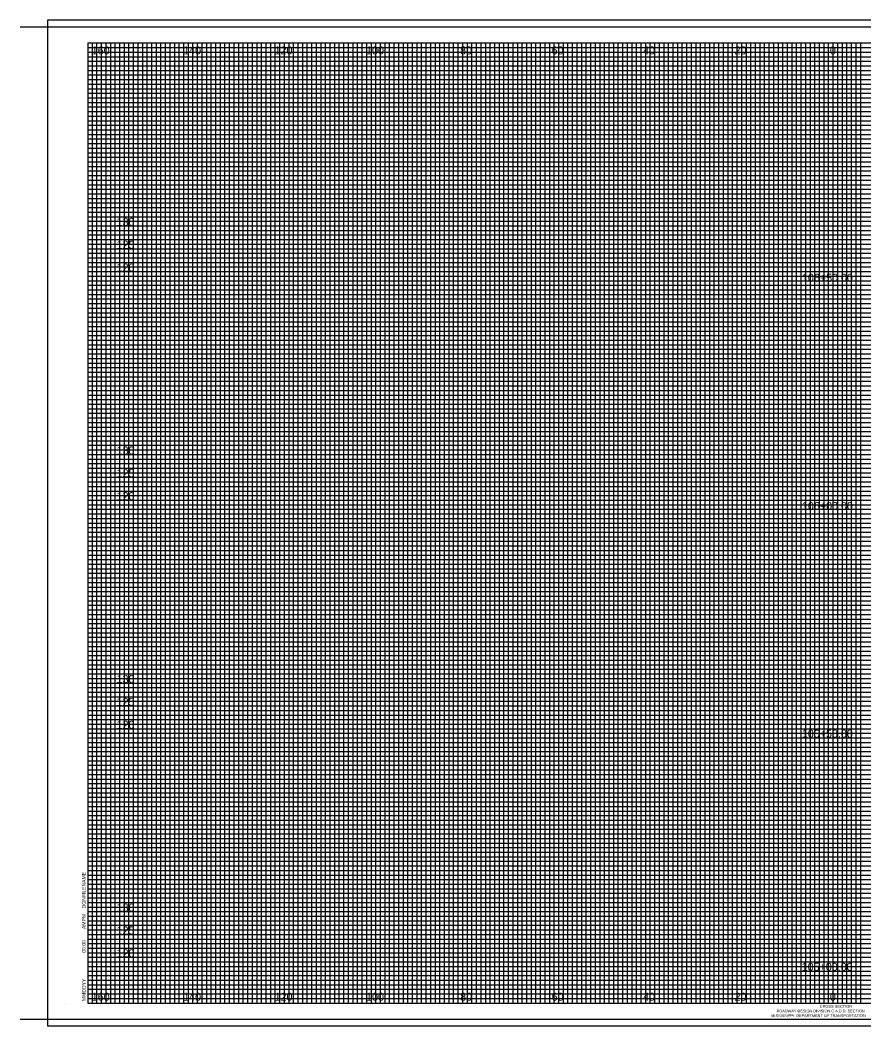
# Model space of a CAD drawing. Extents: x -3604 to 2303, y -13 to 9543.
# Drawn here: x -3604.5 to -3420, y 7144.1 to 7364.1 of the extents above; entities that cross this region are included whole.
import ezdxf

# ---------------------------------------------------------------- set-up
doc = ezdxf.new("R2010")
doc.units = 0
for name, color, linetype in [('SHEET_BORDER', 7, 'Continuous'), ('SHEET_BORDER_TX', 7, 'Continuous'), ('SHEET_DATE_DGN_TX', 7, 'Continuous'), ('SHEET_PLOTTING_SHAPE', 7, 'Continuous'), ('XS_SHEET_LABELS_ELEVATION', 7, 'Continuous'), ('XS_SHEET_LABELS_OFFSET', 7, 'Continuous'), ('XS_SHEET_LABELS_STATION', 7, 'Continuous'), ('XS_SHEET_MAJOR_GRIDS', 7, 'Continuous'), ('XS_SHEET_MEDIUM_GRIDS', 7, 'Continuous'), ('XS_SHEET_MINOR_GRIDS', 7, 'Continuous')]:
    doc.layers.add(name, color=color, linetype=linetype)

msp = doc.modelspace()

# ---------------------------------------------------------------- linework, layer by layer
at = {"layer": 'SHEET_BORDER'}
for p, q in [((-3604.48, 7362.59), (-3252.48, 7362.59)), ((-3589.68, 7359.09), (-3254.68, 7359.09)), ((-3589.68, 7359.09), (-3589.68, 7149.09)), ((-3445.68, 7149.09), (-3445.68, 7359.09)), ((-3594.68, 7149.09), (-3594.68, 7149.09)), ((-3589.68, 7149.09), (-3254.68, 7149.09)), ((-3604.48, 7145.59), (-3252.48, 7145.59))]:
    msp.add_line(p, q, dxfattribs=at)
at = {"layer": 'SHEET_PLOTTING_SHAPE'}
msp.add_lwpolyline([(-3598.48, 7144.09), (-3252.48, 7144.09), (-3252.48, 7364.09), (-3598.48, 7364.09)], close=True, dxfattribs=at)
at = {"layer": 'XS_SHEET_MAJOR_GRIDS'}
for p, q in [((-3584.68, 7149.09), (-3584.68, 7359.09)), ((-3574.68, 7149.09), (-3574.68, 7359.09)), ((-3564.68, 7149.09), (-3564.68, 7359.09)), ((-3554.68, 7149.09), (-3554.68, 7359.09)), ((-3544.68, 7149.09), (-3544.68, 7359.09)), ((-3534.68, 7149.09), (-3534.68, 7359.09)), ((-3524.68, 7149.09), (-3524.68, 7359.09)), ((-3514.68, 7149.09), (-3514.68, 7359.09)), ((-3504.68, 7149.09), (-3504.68, 7359.09)), ((-3494.68, 7149.09), (-3494.68, 7359.09)), ((-3484.68, 7149.09), (-3484.68, 7359.09)), ((-3474.68, 7149.09), (-3474.68, 7359.09)), ((-3464.68, 7149.09), (-3464.68, 7359.09)), ((-3454.68, 7149.09), (-3454.68, 7359.09)), ((-3444.68, 7149.09), (-3444.68, 7359.09)), ((-3434.68, 7149.09), (-3434.68, 7359.09)), ((-3424.68, 7149.09), (-3424.68, 7359.09)), ((-3589.68, 7349.09), (-3254.68, 7349.09)), ((-3589.68, 7339.09), (-3254.68, 7339.09)), ((-3589.68, 7329.09), (-3254.68, 7329.09)), ((-3589.68, 7319.09), (-3254.68, 7319.09)), ((-3589.68, 7309.09), (-3254.68, 7309.09)), ((-3589.68, 7299.09), (-3254.68, 7299.09)), ((-3589.68, 7289.09), (-3254.68, 7289.09)), ((-3589.68, 7279.09), (-3254.68, 7279.09)), ((-3589.68, 7269.09), (-3254.68, 7269.09)), ((-3589.68, 7259.09), (-3254.68, 7259.09)), ((-3589.68, 7249.09), (-3254.68, 7249.09)), ((-3589.68, 7239.09), (-3254.68, 7239.09)), ((-3589.68, 7229.09), (-3254.68, 7229.09)), ((-3589.68, 7219.09), (-3254.68, 7219.09)), ((-3589.68, 7209.09), (-3254.68, 7209.09)), ((-3589.68, 7199.09), (-3254.68, 7199.09)), ((-3589.68, 7189.09), (-3254.68, 7189.09)), ((-3589.68, 7179.09), (-3254.68, 7179.09)), ((-3589.68, 7169.09), (-3254.68, 7169.09)), ((-3589.68, 7159.09), (-3254.68, 7159.09))]:
    msp.add_line(p, q, dxfattribs=at)
at = {"layer": 'XS_SHEET_MEDIUM_GRIDS'}
for p, q in [((-3579.68, 7149.09), (-3579.68, 7359.09)), ((-3569.68, 7149.09), (-3569.68, 7359.09)), ((-3559.68, 7149.09), (-3559.68, 7359.09)), ((-3549.68, 7149.09), (-3549.68, 7359.09)), ((-3539.68, 7149.09), (-3539.68, 7359.09)), ((-3529.68, 7149.09), (-3529.68, 7359.09)), ((-3519.68, 7149.09), (-3519.68, 7359.09)), ((-3509.68, 7149.09), (-3509.68, 7359.09)), ((-3499.68, 7149.09), (-3499.68, 7359.09)), ((-3489.68, 7149.09), (-3489.68, 7359.09)), ((-3479.68, 7149.09), (-3479.68, 7359.09)), ((-3469.68, 7149.09), (-3469.68, 7359.09)), ((-3459.68, 7149.09), (-3459.68, 7359.09)), ((-3449.68, 7149.09), (-3449.68, 7359.09)), ((-3439.68, 7149.09), (-3439.68, 7359.09)), ((-3429.68, 7149.09), (-3429.68, 7359.09)), ((-3589.68, 7354.09), (-3281.68, 7354.09)), ((-3589.68, 7344.09), (-3254.68, 7344.09)), ((-3589.68, 7334.09), (-3254.68, 7334.09)), ((-3589.68, 7324.09), (-3254.68, 7324.09)), ((-3589.68, 7314.09), (-3254.68, 7314.09)), ((-3589.68, 7304.09), (-3254.68, 7304.09)), ((-3589.68, 7294.09), (-3254.68, 7294.09)), ((-3589.68, 7284.09), (-3254.68, 7284.09)), ((-3589.68, 7274.09), (-3254.68, 7274.09)), ((-3589.68, 7264.09), (-3254.68, 7264.09)), ((-3589.68, 7254.09), (-3254.68, 7254.09)), ((-3589.68, 7244.09), (-3254.68, 7244.09)), ((-3589.68, 7234.09), (-3254.68, 7234.09)), ((-3589.68, 7224.09), (-3254.68, 7224.09)), ((-3589.68, 7214.09), (-3254.68, 7214.09)), ((-3589.68, 7204.09), (-3254.68, 7204.09)), ((-3589.68, 7194.09), (-3254.68, 7194.09)), ((-3589.68, 7184.09), (-3254.68, 7184.09)), ((-3589.68, 7174.09), (-3254.68, 7174.09)), ((-3589.68, 7164.09), (-3254.68, 7164.09)), ((-3589.68, 7154.09), (-3264.68, 7154.09))]:
    msp.add_line(p, q, dxfattribs=at)
at = {"layer": 'XS_SHEET_MINOR_GRIDS'}
for p, q in [((-3588.68, 7149.09), (-3588.68, 7359.09)), ((-3587.68, 7149.09), (-3587.68, 7359.09)), ((-3586.68, 7149.09), (-3586.68, 7359.09)), ((-3585.68, 7149.09), (-3585.68, 7359.09)), ((-3583.68, 7149.09), (-3583.68, 7359.09)), ((-3582.68, 7149.09), (-3582.68, 7359.09)), ((-3581.68, 7149.09), (-3581.68, 7359.09)), ((-3580.68, 7149.09), (-3580.68, 7359.09)), ((-3578.68, 7149.09), (-3578.68, 7359.09)), ((-3577.68, 7149.09), (-3577.68, 7359.09)), ((-3576.68, 7149.09), (-3576.68, 7359.09)), ((-3575.68, 7149.09), (-3575.68, 7359.09)), ((-3573.68, 7149.09), (-3573.68, 7359.09)), ((-3572.68, 7149.09), (-3572.68, 7359.09)), ((-3571.68, 7149.09), (-3571.68, 7359.09)), ((-3570.68, 7149.09), (-3570.68, 7359.09)), ((-3568.68, 7149.09), (-3568.68, 7359.09)), ((-3567.68, 7149.09), (-3567.68, 7359.09)), ((-3566.68, 7149.09), (-3566.68, 7359.09)), ((-3565.68, 7149.09), (-3565.68, 7359.09)), ((-3563.68, 7149.09), (-3563.68, 7359.09)), ((-3562.68, 7149.09), (-3562.68, 7359.09)), ((-3561.68, 7149.09), (-3561.68, 7359.09)), ((-3560.68, 7149.09), (-3560.68, 7359.09)), ((-3558.68, 7149.09), (-3558.68, 7359.09)), ((-3557.68, 7149.09), (-3557.68, 7359.09)), ((-3556.68, 7149.09), (-3556.68, 7359.09)), ((-3555.68, 7149.09), (-3555.68, 7359.09)), ((-3553.68, 7149.09), (-3553.68, 7359.09)), ((-3552.68, 7149.09), (-3552.68, 7359.09)), ((-3551.68, 7149.09), (-3551.68, 7359.09)), ((-3550.68, 7149.09), (-3550.68, 7359.09)), ((-3548.68, 7149.09), (-3548.68, 7359.09)), ((-3547.68, 7149.09), (-3547.68, 7359.09)), ((-3546.68, 7149.09), (-3546.68, 7359.09)), ((-3545.68, 7149.09), (-3545.68, 7359.09)), ((-3543.68, 7149.09), (-3543.68, 7359.09)), ((-3542.68, 7149.09), (-3542.68, 7359.09)), ((-3541.68, 7149.09), (-3541.68, 7359.09)), ((-3540.68, 7149.09), (-3540.68, 7359.09)), ((-3538.68, 7149.09), (-3538.68, 7359.09)), ((-3537.68, 7149.09), (-3537.68, 7359.09)), ((-3536.68, 7149.09), (-3536.68, 7359.09)), ((-3535.68, 7149.09), (-3535.68, 7359.09)), ((-3533.68, 7149.09), (-3533.68, 7359.09)), ((-3532.68, 7149.09), (-3532.68, 7359.09)), ((-3531.68, 7149.09), (-3531.68, 7359.09)), ((-3530.68, 7149.09), (-3530.68, 7359.09)), ((-3528.68, 7149.09), (-3528.68, 7359.09)), ((-3527.68, 7149.09), (-3527.68, 7359.09)), ((-3526.68, 7149.09), (-3526.68, 7359.09)), ((-3525.68, 7149.09), (-3525.68, 7359.09)), ((-3523.68, 7149.09), (-3523.68, 7359.09)), ((-3522.68, 7149.09), (-3522.68, 7359.09)), ((-3521.68, 7149.09), (-3521.68, 7359.09)), ((-3520.68, 7149.09), (-3520.68, 7359.09)), ((-3518.68, 7149.09), (-3518.68, 7359.09)), ((-3517.68, 7149.09), (-3517.68, 7359.09)), ((-3516.68, 7149.09), (-3516.68, 7359.09)), ((-3515.68, 7149.09), (-3515.68, 7359.09)), ((-3513.68, 7149.09), (-3513.68, 7359.09)), ((-3512.68, 7149.09), (-3512.68, 7359.09)), ((-3511.68, 7149.09), (-3511.68, 7359.09)), ((-3510.68, 7149.09), (-3510.68, 7359.09)), ((-3508.68, 7149.09), (-3508.68, 7359.09)), ((-3507.68, 7149.09), (-3507.68, 7359.09)), ((-3506.68, 7149.09), (-3506.68, 7359.09)), ((-3505.68, 7149.09), (-3505.68, 7359.09)), ((-3503.68, 7149.09), (-3503.68, 7359.09)), ((-3502.68, 7149.09), (-3502.68, 7359.09)), ((-3501.68, 7149.09), (-3501.68, 7359.09)), ((-3500.68, 7149.09), (-3500.68, 7359.09)), ((-3498.68, 7149.09), (-3498.68, 7359.09)), ((-3497.68, 7149.09), (-3497.68, 7359.09)), ((-3496.68, 7149.09), (-3496.68, 7359.09)), ((-3495.68, 7149.09), (-3495.68, 7359.09)), ((-3493.68, 7149.09), (-3493.68, 7359.09)), ((-3492.68, 7149.09), (-3492.68, 7359.09)), ((-3491.68, 7149.09), (-3491.68, 7359.09)), ((-3490.68, 7149.09), (-3490.68, 7359.09)), ((-3488.68, 7149.09), (-3488.68, 7359.09)), ((-3487.68, 7149.09), (-3487.68, 7359.09)), ((-3486.68, 7149.09), (-3486.68, 7359.09)), ((-3485.68, 7149.09), (-3485.68, 7359.09)), ((-3483.68, 7149.09), (-3483.68, 7359.09)), ((-3482.68, 7149.09), (-3482.68, 7359.09)), ((-3481.68, 7149.09), (-3481.68, 7359.09)), ((-3480.68, 7149.09), (-3480.68, 7359.09)), ((-3478.68, 7149.09), (-3478.68, 7359.09)), ((-3477.68, 7149.09), (-3477.68, 7359.09)), ((-3476.68, 7149.09), (-3476.68, 7359.09)), ((-3475.68, 7149.09), (-3475.68, 7359.09)), ((-3473.68, 7149.09), (-3473.68, 7359.09)), ((-3472.68, 7149.09), (-3472.68, 7359.09)), ((-3471.68, 7149.09), (-3471.68, 7359.09)), ((-3470.68, 7149.09), (-3470.68, 7359.09)), ((-3468.68, 7149.09), (-3468.68, 7359.09)), ((-3467.68, 7149.09), (-3467.68, 7359.09)), ((-3466.68, 7149.09), (-3466.68, 7359.09)), ((-3465.68, 7149.09), (-3465.68, 7359.09)), ((-3463.68, 7149.09), (-3463.68, 7359.09)), ((-3462.68, 7149.09), (-3462.68, 7359.09)), ((-3461.68, 7149.09), (-3461.68, 7359.09)), ((-3460.68, 7149.09), (-3460.68, 7359.09)), ((-3458.68, 7149.09), (-3458.68, 7359.09)), ((-3457.68, 7149.09), (-3457.68, 7359.09)), ((-3456.68, 7149.09), (-3456.68, 7359.09)), ((-3455.68, 7149.09), (-3455.68, 7359.09)), ((-3453.68, 7149.09), (-3453.68, 7359.09)), ((-3452.68, 7149.09), (-3452.68, 7359.09)), ((-3451.68, 7149.09), (-3451.68, 7359.09)), ((-3450.68, 7149.09), (-3450.68, 7359.09)), ((-3448.68, 7149.09), (-3448.68, 7359.09)), ((-3447.68, 7149.09), (-3447.68, 7359.09)), ((-3446.68, 7149.09), (-3446.68, 7359.09)), ((-3443.68, 7149.09), (-3443.68, 7359.09)), ((-3442.68, 7149.09), (-3442.68, 7359.09)), ((-3441.68, 7149.09), (-3441.68, 7359.09)), ((-3440.68, 7149.09), (-3440.68, 7359.09)), ((-3438.68, 7149.09), (-3438.68, 7359.09)), ((-3437.68, 7149.09), (-3437.68, 7359.09)), ((-3436.68, 7149.09), (-3436.68, 7359.09)), ((-3435.68, 7149.09), (-3435.68, 7359.09)), ((-3433.68, 7149.09), (-3433.68, 7359.09)), ((-3432.68, 7149.09), (-3432.68, 7359.09)), ((-3431.68, 7149.09), (-3431.68, 7359.09)), ((-3430.68, 7149.09), (-3430.68, 7359.09)), ((-3428.68, 7149.09), (-3428.68, 7359.09)), ((-3427.68, 7149.09), (-3427.68, 7359.09)), ((-3426.68, 7149.09), (-3426.68, 7359.09)), ((-3425.68, 7149.09), (-3425.68, 7359.09)), ((-3423.68, 7149.09), (-3423.68, 7359.09)), ((-3422.68, 7149.09), (-3422.68, 7359.09)), ((-3421.68, 7149.09), (-3421.68, 7359.09)), ((-3420.68, 7149.09), (-3420.68, 7359.09)), ((-3589.68, 7358.09), (-3281.68, 7358.09)), ((-3589.68, 7357.09), (-3281.68, 7357.09)), ((-3589.68, 7356.09), (-3281.68, 7356.09)), ((-3589.68, 7355.09), (-3281.68, 7355.09)), ((-3589.68, 7353.09), (-3281.68, 7353.09)), ((-3589.68, 7352.09), (-3281.68, 7352.09)), ((-3589.68, 7351.09), (-3281.68, 7351.09)), ((-3589.68, 7350.09), (-3254.68, 7350.09)), ((-3589.68, 7348.09), (-3254.68, 7348.09)), ((-3589.68, 7347.09), (-3254.68, 7347.09)), ((-3589.68, 7346.09), (-3254.68, 7346.09)), ((-3589.68, 7345.09), (-3254.68, 7345.09)), ((-3589.68, 7343.09), (-3254.68, 7343.09)), ((-3589.68, 7342.09), (-3254.68, 7342.09)), ((-3589.68, 7341.09), (-3254.68, 7341.09)), ((-3589.68, 7340.09), (-3254.68, 7340.09)), ((-3589.68, 7338.09), (-3254.68, 7338.09)), ((-3589.68, 7337.09), (-3254.68, 7337.09)), ((-3589.68, 7336.09), (-3254.68, 7336.09)), ((-3589.68, 7335.09), (-3254.68, 7335.09)), ((-3589.68, 7333.09), (-3254.68, 7333.09)), ((-3589.68, 7332.09), (-3254.68, 7332.09)), ((-3589.68, 7331.09), (-3254.68, 7331.09)), ((-3589.68, 7330.09), (-3254.68, 7330.09)), ((-3589.68, 7328.09), (-3254.68, 7328.09)), ((-3589.68, 7327.09), (-3254.68, 7327.09)), ((-3589.68, 7326.09), (-3254.68, 7326.09)), ((-3589.68, 7325.09), (-3254.68, 7325.09)), ((-3589.68, 7323.09), (-3254.68, 7323.09)), ((-3589.68, 7322.09), (-3254.68, 7322.09)), ((-3589.68, 7321.09), (-3254.68, 7321.09)), ((-3589.68, 7320.09), (-3254.68, 7320.09)), ((-3589.68, 7318.09), (-3254.68, 7318.09)), ((-3589.68, 7317.09), (-3254.68, 7317.09)), ((-3589.68, 7316.09), (-3254.68, 7316.09)), ((-3589.68, 7315.09), (-3254.68, 7315.09)), ((-3589.68, 7313.09), (-3254.68, 7313.09)), ((-3589.68, 7312.09), (-3254.68, 7312.09)), ((-3589.68, 7311.09), (-3254.68, 7311.09)), ((-3589.68, 7310.09), (-3254.68, 7310.09)), ((-3589.68, 7308.09), (-3254.68, 7308.09)), ((-3589.68, 7307.09), (-3254.68, 7307.09)), ((-3589.68, 7306.09), (-3254.68, 7306.09)), ((-3589.68, 7305.09), (-3254.68, 7305.09)), ((-3589.68, 7303.09), (-3254.68, 7303.09)), ((-3589.68, 7302.09), (-3254.68, 7302.09)), ((-3589.68, 7301.09), (-3254.68, 7301.09)), ((-3589.68, 7300.09), (-3254.68, 7300.09)), ((-3589.68, 7298.09), (-3254.68, 7298.09)), ((-3589.68, 7297.09), (-3254.68, 7297.09)), ((-3589.68, 7296.09), (-3254.68, 7296.09)), ((-3589.68, 7295.09), (-3254.68, 7295.09)), ((-3589.68, 7293.09), (-3254.68, 7293.09)), ((-3589.68, 7292.09), (-3254.68, 7292.09)), ((-3589.68, 7291.09), (-3254.68, 7291.09)), ((-3589.68, 7290.09), (-3254.68, 7290.09)), ((-3589.68, 7288.09), (-3254.68, 7288.09)), ((-3589.68, 7287.09), (-3254.68, 7287.09)), ((-3589.68, 7286.09), (-3254.68, 7286.09)), ((-3589.68, 7285.09), (-3254.68, 7285.09)), ((-3589.68, 7283.09), (-3254.68, 7283.09)), ((-3589.68, 7282.09), (-3254.68, 7282.09)), ((-3589.68, 7281.09), (-3254.68, 7281.09)), ((-3589.68, 7280.09), (-3254.68, 7280.09)), ((-3589.68, 7278.09), (-3254.68, 7278.09)), ((-3589.68, 7277.09), (-3254.68, 7277.09)), ((-3589.68, 7276.09), (-3254.68, 7276.09)), ((-3589.68, 7275.09), (-3254.68, 7275.09)), ((-3589.68, 7273.09), (-3254.68, 7273.09)), ((-3589.68, 7272.09), (-3254.68, 7272.09)), ((-3589.68, 7271.09), (-3254.68, 7271.09)), ((-3589.68, 7270.09), (-3254.68, 7270.09)), ((-3589.68, 7268.09), (-3254.68, 7268.09)), ((-3589.68, 7267.09), (-3254.68, 7267.09)), ((-3589.68, 7266.09), (-3254.68, 7266.09)), ((-3589.68, 7265.09), (-3254.68, 7265.09)), ((-3589.68, 7263.09), (-3254.68, 7263.09)), ((-3589.68, 7262.09), (-3254.68, 7262.09)), ((-3589.68, 7261.09), (-3254.68, 7261.09)), ((-3589.68, 7260.09), (-3254.68, 7260.09)), ((-3589.68, 7258.09), (-3254.68, 7258.09)), ((-3589.68, 7257.09), (-3254.68, 7257.09)), ((-3589.68, 7256.09), (-3254.68, 7256.09)), ((-3589.68, 7255.09), (-3254.68, 7255.09)), ((-3589.68, 7253.09), (-3254.68, 7253.09)), ((-3589.68, 7252.09), (-3254.68, 7252.09)), ((-3589.68, 7251.09), (-3254.68, 7251.09)), ((-3589.68, 7250.09), (-3254.68, 7250.09)), ((-3589.68, 7248.09), (-3254.68, 7248.09)), ((-3589.68, 7247.09), (-3254.68, 7247.09)), ((-3589.68, 7246.09), (-3254.68, 7246.09)), ((-3589.68, 7245.09), (-3254.68, 7245.09)), ((-3589.68, 7243.09), (-3254.68, 7243.09)), ((-3589.68, 7242.09), (-3254.68, 7242.09)), ((-3589.68, 7241.09), (-3254.68, 7241.09)), ((-3589.68, 7240.09), (-3254.68, 7240.09)), ((-3589.68, 7238.09), (-3254.68, 7238.09)), ((-3589.68, 7237.09), (-3254.68, 7237.09)), ((-3589.68, 7236.09), (-3254.68, 7236.09)), ((-3589.68, 7235.09), (-3254.68, 7235.09)), ((-3589.68, 7233.09), (-3254.68, 7233.09)), ((-3589.68, 7232.09), (-3254.68, 7232.09)), ((-3589.68, 7231.09), (-3254.68, 7231.09)), ((-3589.68, 7230.09), (-3254.68, 7230.09)), ((-3589.68, 7228.09), (-3254.68, 7228.09)), ((-3589.68, 7227.09), (-3254.68, 7227.09)), ((-3589.68, 7226.09), (-3254.68, 7226.09)), ((-3589.68, 7225.09), (-3254.68, 7225.09)), ((-3589.68, 7223.09), (-3254.68, 7223.09)), ((-3589.68, 7222.09), (-3254.68, 7222.09)), ((-3589.68, 7221.09), (-3254.68, 7221.09)), ((-3589.68, 7220.09), (-3254.68, 7220.09)), ((-3589.68, 7218.09), (-3254.68, 7218.09)), ((-3589.68, 7217.09), (-3254.68, 7217.09)), ((-3589.68, 7216.09), (-3254.68, 7216.09)), ((-3589.68, 7215.09), (-3254.68, 7215.09)), ((-3589.68, 7213.09), (-3254.68, 7213.09)), ((-3589.68, 7212.09), (-3254.68, 7212.09)), ((-3589.68, 7211.09), (-3254.68, 7211.09)), ((-3589.68, 7210.09), (-3254.68, 7210.09)), ((-3589.68, 7208.09), (-3254.68, 7208.09)), ((-3589.68, 7207.09), (-3254.68, 7207.09)), ((-3589.68, 7206.09), (-3254.68, 7206.09)), ((-3589.68, 7205.09), (-3254.68, 7205.09)), ((-3589.68, 7203.09), (-3254.68, 7203.09)), ((-3589.68, 7202.09), (-3254.68, 7202.09)), ((-3589.68, 7201.09), (-3254.68, 7201.09)), ((-3589.68, 7200.09), (-3254.68, 7200.09)), ((-3589.68, 7198.09), (-3254.68, 7198.09)), ((-3589.68, 7197.09), (-3254.68, 7197.09)), ((-3589.68, 7196.09), (-3254.68, 7196.09)), ((-3589.68, 7195.09), (-3254.68, 7195.09)), ((-3589.68, 7193.09), (-3254.68, 7193.09)), ((-3589.68, 7192.09), (-3254.68, 7192.09)), ((-3589.68, 7191.09), (-3254.68, 7191.09)), ((-3589.68, 7190.09), (-3254.68, 7190.09)), ((-3589.68, 7188.09), (-3254.68, 7188.09)), ((-3589.68, 7187.09), (-3254.68, 7187.09)), ((-3589.68, 7186.09), (-3254.68, 7186.09)), ((-3589.68, 7185.09), (-3254.68, 7185.09)), ((-3589.68, 7183.09), (-3254.68, 7183.09)), ((-3589.68, 7182.09), (-3254.68, 7182.09)), ((-3589.68, 7181.09), (-3254.68, 7181.09)), ((-3589.68, 7180.09), (-3254.68, 7180.09)), ((-3589.68, 7178.09), (-3254.68, 7178.09)), ((-3589.68, 7177.09), (-3254.68, 7177.09)), ((-3589.68, 7176.09), (-3254.68, 7176.09)), ((-3589.68, 7175.09), (-3254.68, 7175.09)), ((-3589.68, 7173.09), (-3254.68, 7173.09)), ((-3589.68, 7172.09), (-3254.68, 7172.09)), ((-3589.68, 7171.09), (-3254.68, 7171.09)), ((-3589.68, 7170.09), (-3254.68, 7170.09)), ((-3589.68, 7170.09), (-3254.68, 7170.09)), ((-3589.68, 7170.09), (-3254.68, 7170.09)), ((-3589.68, 7168.09), (-3254.68, 7168.09)), ((-3589.68, 7167.09), (-3254.68, 7167.09)), ((-3589.68, 7166.09), (-3254.68, 7166.09)), ((-3589.68, 7165.09), (-3254.68, 7165.09)), ((-3589.68, 7163.09), (-3254.68, 7163.09)), ((-3589.68, 7162.09), (-3254.68, 7162.09)), ((-3589.68, 7161.09), (-3254.68, 7161.09)), ((-3589.68, 7160.09), (-3254.68, 7160.09)), ((-3589.68, 7158.09), (-3264.68, 7158.09)), ((-3589.68, 7157.09), (-3264.68, 7157.09)), ((-3589.68, 7156.09), (-3264.68, 7156.09)), ((-3589.68, 7155.09), (-3264.68, 7155.09)), ((-3589.68, 7155.09), (-3264.68, 7155.09)), ((-3589.68, 7155.09), (-3264.68, 7155.09)), ((-3589.68, 7153.09), (-3264.68, 7153.09)), ((-3589.68, 7152.09), (-3264.68, 7152.09)), ((-3589.68, 7151.09), (-3264.68, 7151.09)), ((-3589.68, 7150.09), (-3264.68, 7150.09))]:
    msp.add_line(p, q, dxfattribs=at)

# ---------------------------------------------------------------- texts
at = {"layer": 'SHEET_BORDER_TX'}
for s, height, p in [('CROSS SECTION', 0.62, (-3429.64, 7148.06)), ('MISSISSIPPI  DEPARTMENT OF TRANSPORTATION', 0.61, (-3440.24, 7146.01)), ('ROADWAY DESIGN DIVISION C.A.D.D. SECTION', 0.61, (-3439.08, 7147.04))]:
    msp.add_text(s, height=height, dxfattribs=at).set_placement(p)
at = {"layer": 'SHEET_DATE_DGN_TX'}
for s, p in [('DGNFILENAME', (-3590.15, 7169.79)), ('AMPM', (-3590.15, 7165.27)), ('00:00', (-3590.15, 7160.09)), ('MMDDYY', (-3590.15, 7149.51))]:
    msp.add_text(s, height=0.8, rotation=90, dxfattribs=at).set_placement(p)
at = {"layer": 'XS_SHEET_LABELS_ELEVATION'}
for s, p in [('  130  ', (-3584.68, 7319.09)), ('  125  ', (-3584.68, 7314.09)), ('  120  ', (-3584.68, 7309.09)), ('  130  ', (-3584.68, 7269.09)), ('  125  ', (-3584.68, 7264.09)), ('  120  ', (-3584.68, 7259.09)), ('  130  ', (-3584.68, 7219.09)), ('  125  ', (-3584.68, 7214.09)), ('  120  ', (-3584.68, 7209.09)), ('  130  ', (-3584.68, 7169.09)), ('  125  ', (-3584.68, 7164.09)), ('  120  ', (-3584.68, 7159.09))]:
    msp.add_text(s, height=1.75, dxfattribs=at).set_placement(p)
at = {"layer": 'XS_SHEET_LABELS_OFFSET'}
for s, p in [('  160  ', (-3590.11, 7356.59)), ('  140  ', (-3570.13, 7356.59)), ('  120  ', (-3550.13, 7356.59)), ('  100  ', (-3530.13, 7356.59)), ('  80  ', (-3509.56, 7356.59)), ('  60  ', (-3489.55, 7356.59)), ('  40  ', (-3469.56, 7356.59)), ('  20  ', (-3449.56, 7356.59)), ('  0  ', (-3428.71, 7356.59)), ('  0  ', (-3428.71, 7356.59)), ('  160  ', (-3590.11, 7149.59)), ('  140  ', (-3570.13, 7149.59)), ('  120  ', (-3550.13, 7149.59)), ('  100  ', (-3530.13, 7149.59)), ('  80  ', (-3509.56, 7149.59)), ('  60  ', (-3489.55, 7149.59)), ('  40  ', (-3469.56, 7149.59)), ('  20  ', (-3449.56, 7149.59)), ('  0  ', (-3428.71, 7149.59)), ('  0  ', (-3428.71, 7149.59))]:
    msp.add_text(s, height=1.75, dxfattribs=at).set_placement(p)
at = {"layer": 'XS_SHEET_LABELS_STATION'}
for s, p in [('  106+50.00  ', (-3434.81, 7306.85)), ('  106+00.00  ', (-3434.81, 7256.94)), ('  105+50.00  ', (-3434.83, 7207.14)), ('  105+00.00  ', (-3434.87, 7156.14))]:
    msp.add_text(s, height=1.75, dxfattribs=at).set_placement(p)

doc.saveas('drawing.dxf')
